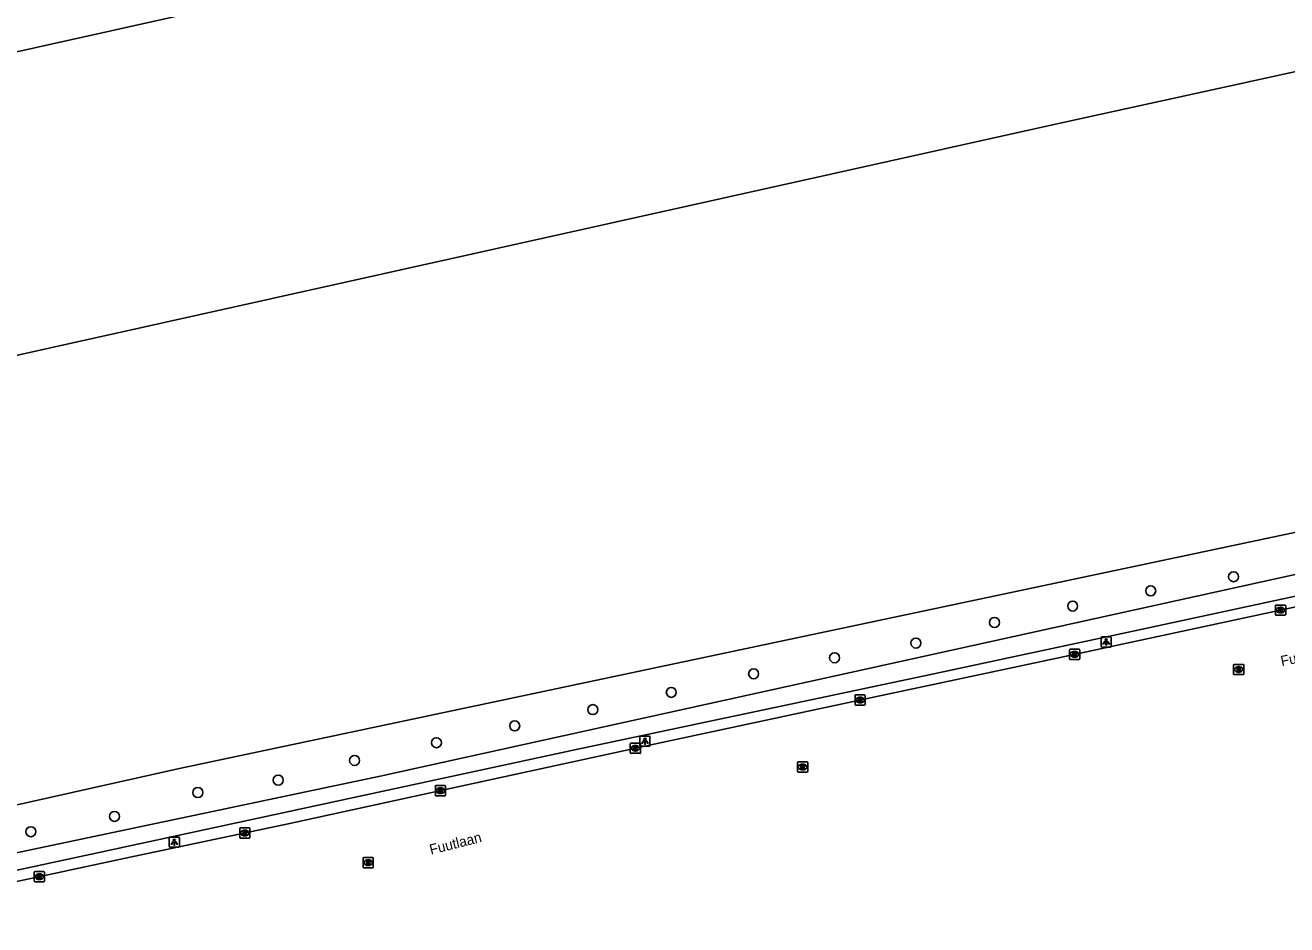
# Model space of a CAD drawing. Extents: x 161477 to 163040, y 383680 to 384868.
# Drawn here: x 161899 to 162022.7, y 383711.9 to 383800 of the extents above; entities that cross this region are included whole.
import ezdxf

# ---------------------------------------------------------------- set-up
doc = ezdxf.new("R2010")
doc.units = 0
for name, color, linetype in [('IMGEO_Boom', 7, 'Continuous'), ('IMGEO_Groenvoorziening', 7, 'Continuous'), ('IMGEO_Hek', 7, 'Continuous'), ('IMGEO_Kolk', 7, 'Continuous'), ('IMGEO_Lichtpunt', 7, 'Continuous'), ('IMGEO_Openbare_ruimte_label', 7, 'Continuous'), ('IMGEO_Pand', 7, 'Continuous'), ('IMGEO_Rijbaan_lokaal_open', 7, 'Continuous'), ('IMGEO_Rioolput', 7, 'Continuous'), ('IMGEO_Voetpad_open', 7, 'Continuous')]:
    doc.layers.add(name, color=color, linetype=linetype)

msp = doc.modelspace()

# ---------------------------------------------------------------- linework, layer by layer
at = {"layer": 'IMGEO_Boom'}
for centre in [(162017.44, 383746.01), (162009.32, 383744.63), (162001.67, 383743.13), (161994.01, 383741.53), (161986.3, 383739.51), (161978.33, 383738.07), (161970.4, 383736.5), (161962.33, 383734.68), (161954.64, 383732.99), (161946.98, 383731.4), (161939.31, 383729.75), (161931.28, 383728.01), (161923.8, 383726.08), (161915.92, 383724.87), (161907.75, 383722.53), (161899.55, 383721.03)]:
    msp.add_circle(centre, 0.489, dxfattribs=at)
at = {"layer": 'IMGEO_Groenvoorziening'}
for points in [[(162298.92, 383814.56), (162261.09, 383802.89), (162253.58, 383800.74), (162226.94, 383794.59), (162215.71, 383792.24), (162200.21, 383788.99), (162072.88, 383760.06), (162061.02, 383757.62), (162034.23, 383752.62), (161913.96, 383727.2), (161882.57, 383720.16), (161862.58, 383715.7), (161851.78, 383713.8), (161847.77, 383713.09), (161846.44, 383712.85), (161845.48, 383712.89), (161845.45, 383711.91)], [(162231.35, 383791.72), (162216.7, 383788.57), (162197.76, 383783.49), (162191.42, 383781.95), (162037.84, 383749.41), (161933.79, 383726.48), (161872.38, 383713.55)]]:
    msp.add_lwpolyline(points, dxfattribs=at)
at = {"layer": 'IMGEO_Hek'}
msp.add_lwpolyline([(161846.44, 383712.85), (161847.77, 383713.09), (161851.78, 383713.8), (161862.58, 383715.7), (161882.57, 383720.16), (161913.96, 383727.2), (162034.23, 383752.62), (162061.02, 383757.62)], dxfattribs=at)
at = {"layer": 'IMGEO_Kolk'}
for p, q in [((162021.55, 383742.31), (162021.55, 383743.17)), ((162021.62, 383743.24), (162022.47, 383743.24)), ((162022.06, 383742.46), (162022.03, 383742.46)), ((162022.04, 383743.02), (162022.06, 383743.02)), ((162022.55, 383743.17), (162022.55, 383742.31)), ((162022.47, 383742.24), (162021.62, 383742.24)), ((162001.35, 383737.98), (162001.35, 383738.83)), ((162001.43, 383738.91), (162002.28, 383738.91)), ((162001.84, 383738.69), (162001.87, 383738.69)), ((162002.36, 383738.83), (162002.36, 383737.98)), ((162002.28, 383737.91), (162001.43, 383737.91)), ((162001.86, 383738.13), (162001.84, 383738.13)), ((161980.34, 383733.5), (161980.34, 383734.36)), ((161980.41, 383734.43), (161981.27, 383734.43)), ((161980.83, 383734.21), (161980.85, 383734.21)), ((161981.34, 383734.36), (161981.34, 383733.5)), ((161981.27, 383733.43), (161980.41, 383733.43)), ((161980.85, 383733.65), (161980.82, 383733.65)), ((161958.31, 383728.78), (161958.31, 383729.63)), ((161958.39, 383729.71), (161959.24, 383729.71)), ((161958.8, 383729.49), (161958.83, 383729.49)), ((161958.82, 383728.93), (161958.8, 383728.93)), ((161959.31, 383729.63), (161959.31, 383728.78)), ((161959.24, 383728.71), (161958.39, 383728.71)), ((161939.2, 383724.62), (161939.2, 383725.48)), ((161939.27, 383725.55), (161940.12, 383725.55)), ((161939.69, 383725.33), (161939.71, 383725.33)), ((161940.2, 383725.48), (161940.2, 383724.62)), ((161940.12, 383724.55), (161939.27, 383724.55)), ((161939.71, 383724.77), (161939.68, 383724.77)), ((161920.1, 383721.4), (161920.95, 383721.4)), ((161920.03, 383720.47), (161920.03, 383721.33)), ((161920.95, 383720.4), (161920.1, 383720.4)), ((161920.51, 383721.18), (161920.54, 383721.18)), ((161920.54, 383720.62), (161920.51, 383720.62)), ((161921.03, 383721.33), (161921.03, 383720.47)), ((161899.89, 383716.19), (161899.89, 383717.05)), ((161899.96, 383717.12), (161900.82, 383717.12)), ((161900.38, 383716.9), (161900.4, 383716.9)), ((161900.89, 383717.05), (161900.89, 383716.19)), ((161900.82, 383716.12), (161899.96, 383716.12)), ((161900.4, 383716.34), (161900.38, 383716.34))]:
    msp.add_line(p, q, dxfattribs=at)
for points in [[(162021.55, 383742.31), (162021.55, 383743.17)], [(162021.62, 383743.24), (162022.47, 383743.24)], [(162021.87, 383742.94), (162021.99, 383742.94), (162021.99, 383742.79), (162022.12, 383742.94), (162022.29, 383742.94), (162022.14, 383742.79), (162022.29, 383742.54), (162022.14, 383742.54), (162022.06, 383742.7), (162021.99, 383742.64), (162021.99, 383742.54), (162021.87, 383742.54), (162021.87, 383742.94)], [(162022.55, 383743.17), (162022.55, 383742.31)], [(162022.47, 383742.24), (162021.62, 383742.24)], [(162001.35, 383737.98), (162001.35, 383738.83)], [(162001.43, 383738.91), (162002.28, 383738.91)], [(162002.36, 383738.83), (162002.36, 383737.98)], [(162002.28, 383737.91), (162001.43, 383737.91)], [(162001.67, 383738.61), (162001.8, 383738.61), (162001.8, 383738.46), (162001.93, 383738.61), (162002.09, 383738.61), (162001.95, 383738.46), (162002.1, 383738.21), (162001.95, 383738.21), (162001.86, 383738.37), (162001.8, 383738.31), (162001.8, 383738.21), (162001.67, 383738.21), (162001.67, 383738.61)], [(161980.34, 383733.5), (161980.34, 383734.36)], [(161980.41, 383734.43), (161981.27, 383734.43)], [(161980.66, 383734.13), (161980.78, 383734.13), (161980.78, 383733.98), (161980.91, 383734.13), (161981.08, 383734.13), (161980.93, 383733.98), (161981.08, 383733.73), (161980.93, 383733.73), (161980.85, 383733.89), (161980.78, 383733.83), (161980.78, 383733.73), (161980.66, 383733.73), (161980.66, 383734.13)], [(161981.34, 383734.36), (161981.34, 383733.5)], [(161981.27, 383733.43), (161980.41, 383733.43)], [(161958.31, 383728.78), (161958.31, 383729.63)], [(161958.39, 383729.71), (161959.24, 383729.71)], [(161958.63, 383729.41), (161958.76, 383729.41), (161958.76, 383729.25), (161958.89, 383729.41), (161959.05, 383729.41), (161958.9, 383729.26), (161959.06, 383729.01), (161958.9, 383729.01), (161958.82, 383729.17), (161958.76, 383729.1), (161958.76, 383729.01), (161958.63, 383729.01), (161958.63, 383729.41)], [(161959.31, 383729.63), (161959.31, 383728.78)], [(161959.24, 383728.71), (161958.39, 383728.71)], [(161939.2, 383724.62), (161939.2, 383725.48)], [(161939.27, 383725.55), (161940.12, 383725.55)], [(161939.52, 383725.25), (161939.64, 383725.25), (161939.64, 383725.1), (161939.77, 383725.25), (161939.94, 383725.25), (161939.79, 383725.1), (161939.94, 383724.85), (161939.79, 383724.85), (161939.71, 383725.01), (161939.64, 383724.95), (161939.64, 383724.85), (161939.52, 383724.85), (161939.52, 383725.25)], [(161940.2, 383725.48), (161940.2, 383724.62)], [(161940.12, 383724.55), (161939.27, 383724.55)], [(161920.1, 383721.4), (161920.95, 383721.4)], [(161920.03, 383720.47), (161920.03, 383721.33)], [(161920.95, 383720.4), (161920.1, 383720.4)], [(161920.35, 383721.1), (161920.47, 383721.1), (161920.47, 383720.95), (161920.6, 383721.1), (161920.76, 383721.1), (161920.62, 383720.95), (161920.77, 383720.7), (161920.62, 383720.7), (161920.53, 383720.86), (161920.47, 383720.8), (161920.47, 383720.7), (161920.35, 383720.7), (161920.35, 383721.1)], [(161921.03, 383721.33), (161921.03, 383720.47)], [(161899.89, 383716.19), (161899.89, 383717.05)], [(161899.96, 383717.12), (161900.82, 383717.12)], [(161900.21, 383716.82), (161900.33, 383716.82), (161900.33, 383716.67), (161900.46, 383716.82), (161900.63, 383716.82), (161900.48, 383716.67), (161900.63, 383716.42), (161900.48, 383716.42), (161900.4, 383716.59), (161900.33, 383716.52), (161900.33, 383716.42), (161900.21, 383716.42), (161900.21, 383716.82)], [(161900.89, 383717.05), (161900.89, 383716.19)], [(161900.82, 383716.12), (161899.96, 383716.12)]]:
    msp.add_lwpolyline(points, dxfattribs=at)
for centre, start, end in [((162021.62, 383743.16), 91.552, 178.448), ((162021.62, 383743.16), 91.552, 178.448), ((162022.47, 383743.16), 1.552, 88.448), ((162022.47, 383743.16), 1.552, 88.448), ((162021.62, 383742.32), 181.552, 268.448), ((162021.62, 383742.32), 181.552, 268.448), ((162022.47, 383742.32), 271.552, 358.448), ((162022.47, 383742.32), 271.552, 358.448), ((162001.43, 383738.83), 91.552, 178.448), ((162001.43, 383738.83), 91.552, 178.448), ((162002.28, 383738.83), 1.552, 88.448), ((162002.28, 383738.83), 1.552, 88.448), ((162001.43, 383737.98), 181.552, 268.448), ((162001.43, 383737.98), 181.552, 268.448), ((162002.28, 383737.98), 271.552, 358.448), ((162002.28, 383737.98), 271.552, 358.448), ((161980.41, 383734.35), 91.552, 178.448), ((161980.41, 383734.35), 91.552, 178.448), ((161981.26, 383734.35), 1.552, 88.448), ((161981.26, 383734.35), 1.552, 88.448), ((161980.41, 383733.5), 181.552, 268.448), ((161980.41, 383733.5), 181.552, 268.448), ((161981.26, 383733.5), 271.552, 358.448), ((161981.26, 383733.5), 271.552, 358.448), ((161958.39, 383729.63), 91.552, 178.448), ((161958.39, 383729.63), 91.552, 178.448), ((161959.24, 383729.63), 1.552, 88.448), ((161959.24, 383729.63), 1.552, 88.448), ((161958.39, 383728.78), 181.552, 268.448), ((161958.39, 383728.78), 181.552, 268.448), ((161959.24, 383728.78), 271.552, 358.448), ((161959.24, 383728.78), 271.552, 358.448), ((161939.27, 383725.47), 91.552, 178.448), ((161939.27, 383725.47), 91.552, 178.448), ((161940.12, 383725.47), 1.552, 88.448), ((161940.12, 383725.47), 1.552, 88.448), ((161939.27, 383724.63), 181.552, 268.448), ((161939.27, 383724.63), 181.552, 268.448), ((161940.12, 383724.63), 271.552, 358.448), ((161940.12, 383724.63), 271.552, 358.448), ((161920.1, 383721.32), 91.552, 178.448), ((161920.1, 383721.32), 91.552, 178.448), ((161920.95, 383721.32), 1.552, 88.448), ((161920.95, 383721.32), 1.552, 88.448), ((161920.1, 383720.48), 181.552, 268.448), ((161920.1, 383720.48), 181.552, 268.448), ((161920.95, 383720.48), 271.552, 358.448), ((161920.95, 383720.48), 271.552, 358.448), ((161899.97, 383717.05), 91.552, 178.448), ((161899.97, 383717.05), 91.552, 178.448), ((161900.81, 383717.05), 1.552, 88.448), ((161900.81, 383717.05), 1.552, 88.448), ((161899.97, 383716.2), 181.552, 268.448), ((161899.97, 383716.2), 181.552, 268.448), ((161900.81, 383716.2), 271.552, 358.448), ((161900.81, 383716.2), 271.552, 358.448)]:
    msp.add_arc(centre, 0.0765, start, end, dxfattribs=at)
for centre, major_axis, ratio, start_param, end_param in [((162022.03, 383742.74), (-0.387, 0.002), 0.722429, 4.712389, 7.853982), ((162022.06, 383742.74), (-0.39, 0.002), 0.717154, 1.570796, 4.712389), ((162001.84, 383738.41), (-0.387, 0.002), 0.722429, 4.712389, 7.853982), ((162001.87, 383738.41), (-0.39, 0.002), 0.717154, 1.570796, 4.712389), ((161980.83, 383733.93), (-0.387, 0.002), 0.722429, 4.712389, 7.853982), ((161980.85, 383733.93), (-0.39, 0.002), 0.717154, 1.570796, 4.712389), ((161958.8, 383729.21), (-0.387, 0.002), 0.722429, 4.712389, 7.853982), ((161958.82, 383729.21), (-0.39, 0.002), 0.717154, 1.570796, 4.712389), ((161939.68, 383725.05), (-0.387, 0.002), 0.722429, 4.712389, 7.853982), ((161939.71, 383725.05), (-0.39, 0.002), 0.717154, 1.570796, 4.712389), ((161920.51, 383720.9), (-0.387, 0.002), 0.722429, 4.712389, 7.853982), ((161920.54, 383720.9), (-0.39, 0.002), 0.717154, 1.570796, 4.712389), ((161900.38, 383716.62), (-0.387, 0.002), 0.722429, 4.712389, 7.853982), ((161900.4, 383716.62), (-0.39, 0.002), 0.717154, 1.570796, 4.712389)]:
    msp.add_ellipse(centre, major_axis=major_axis, ratio=ratio, start_param=start_param, end_param=end_param, dxfattribs=at)
at = {"layer": 'IMGEO_Lichtpunt'}
for p, q in [((162004.45, 383740.02), (162004.45, 383739.21)), ((162004.45, 383740.02), (162004.45, 383739.21)), ((162005.36, 383740.11), (162004.55, 383740.11)), ((162005.36, 383740.11), (162004.55, 383740.11)), ((162005.45, 383739.21), (162005.45, 383740.02)), ((162005.45, 383739.21), (162005.45, 383740.02)), ((162004.55, 383739.11), (162005.36, 383739.11)), ((162004.55, 383739.11), (162005.36, 383739.11)), ((161959.25, 383730.3), (161959.25, 383729.5)), ((161959.25, 383730.3), (161959.25, 383729.5)), ((161960.15, 383730.4), (161959.34, 383730.4)), ((161960.15, 383730.4), (161959.34, 383730.4)), ((161960.24, 383729.5), (161960.24, 383730.3)), ((161960.24, 383729.5), (161960.24, 383730.3)), ((161959.34, 383729.4), (161960.15, 383729.4)), ((161959.34, 383729.4), (161960.15, 383729.4)), ((161913.11, 383720.42), (161913.11, 383719.61)), ((161913.11, 383720.42), (161913.11, 383719.61)), ((161914.01, 383720.51), (161913.21, 383720.51)), ((161914.01, 383720.51), (161913.21, 383720.51)), ((161914.11, 383719.61), (161914.11, 383720.42)), ((161914.11, 383719.61), (161914.11, 383720.42)), ((161913.21, 383719.51), (161914.01, 383719.51)), ((161913.21, 383719.51), (161914.01, 383719.51))]:
    msp.add_line(p, q, dxfattribs=at)
for points in [[(162004.83, 383739.68), (162004.87, 383739.65), (162004.68, 383739.39), (162004.64, 383739.42), (162004.83, 383739.68)], [(162004.93, 383739.63), (162004.98, 383739.63), (162004.98, 383739.31), (162004.93, 383739.31), (162004.93, 383739.63)], [(162005.04, 383739.65), (162005.08, 383739.68), (162005.27, 383739.42), (162005.23, 383739.39), (162005.04, 383739.65)], [(161959.62, 383729.97), (161959.66, 383729.94), (161959.47, 383729.68), (161959.43, 383729.7), (161959.62, 383729.97)], [(161959.72, 383729.92), (161959.77, 383729.92), (161959.77, 383729.6), (161959.72, 383729.6), (161959.72, 383729.92)], [(161959.83, 383729.94), (161959.87, 383729.97), (161960.06, 383729.7), (161960.02, 383729.68), (161959.83, 383729.94)], [(161913.49, 383720.08), (161913.53, 383720.05), (161913.34, 383719.79), (161913.3, 383719.82), (161913.49, 383720.08)], [(161913.59, 383720.03), (161913.64, 383720.03), (161913.64, 383719.71), (161913.59, 383719.71), (161913.59, 383720.03)], [(161913.7, 383720.05), (161913.74, 383720.08), (161913.92, 383719.82), (161913.89, 383719.79), (161913.7, 383720.05)]]:
    msp.add_lwpolyline(points, dxfattribs=at)
for centre in [(162004.95, 383739.81), (161959.75, 383730.1), (161913.61, 383720.21)]:
    msp.add_circle(centre, 0.0994, dxfattribs=at)
for centre, start, end in [((162004.55, 383740.02), 90, 180), ((162004.55, 383740.02), 90, 180), ((162005.36, 383740.02), 0, 90), ((162005.36, 383740.02), 0, 90), ((162004.55, 383739.21), 180, 270), ((162004.55, 383739.21), 180, 270), ((162005.36, 383739.21), 270, 0), ((162005.36, 383739.21), 270, 360), ((161959.34, 383730.3), 90, 180), ((161959.34, 383730.3), 90, 180), ((161960.15, 383730.3), 0, 90), ((161960.15, 383730.3), 0, 90), ((161959.34, 383729.5), 180, 270), ((161959.34, 383729.5), 180, 270), ((161960.15, 383729.5), 270, 0), ((161960.15, 383729.5), 270, 360), ((161913.21, 383720.42), 90, 180), ((161913.21, 383720.42), 90, 180), ((161914.01, 383720.42), 0, 90), ((161914.01, 383720.42), 0, 90), ((161913.21, 383719.61), 180, 270), ((161913.21, 383719.61), 180, 270), ((161914.01, 383719.61), 270, 0), ((161914.01, 383719.61), 270, 360)]:
    msp.add_arc(centre, 0.0946, start, end, dxfattribs=at)
at = {"layer": 'IMGEO_Pand'}
for points in [[(161884.31, 383793.82), (161888.73, 383773.98), (161886.05, 383773.38), (161886.3, 383772.28), (161885.88, 383772.17), (161885.51, 383773.82), (161859.41, 383768), (161862.46, 383754.35), (161888.64, 383760.19), (161888.12, 383762.5), (161887.37, 383765.86), (161890.33, 383766.52), (161890.45, 383765.98), (162000, 383790.34), (162126.91, 383818.18), (162134.33, 383819.8), (162130.48, 383837.21), (162140.9, 383839.53), (162139.81, 383844.85)], [(162088.04, 383839.79), (162000, 383820.13), (161884.78, 383794.45), (161884.66, 383795.01), (161884.29, 383794.93), (161884.34, 383794.72)]]:
    msp.add_lwpolyline(points, dxfattribs=at)
at = {"layer": 'IMGEO_Rijbaan_lokaal_open'}
msp.add_lwpolyline([(162038.61, 383746.29), (162000, 383738.01), (161982.31, 383734.24), (161961.39, 383729.76), (161941.41, 383725.42), (161924.76, 383721.79), (161909.3, 383718.55), (161896.63, 383715.81)], dxfattribs=at)
at = {"layer": 'IMGEO_Rioolput'}
for p, q in [((162017.45, 383736.49), (162017.45, 383737.35)), ((162017.52, 383737.42), (162018.37, 383737.42)), ((162018.37, 383736.42), (162017.52, 383736.42)), ((162017.93, 383737.2), (162017.96, 383737.2)), ((162017.96, 383736.64), (162017.93, 383736.64)), ((162018.45, 383737.35), (162018.45, 383736.49)), ((161974.7, 383726.95), (161974.7, 383727.8)), ((161974.77, 383727.88), (161975.62, 383727.88)), ((161975.18, 383727.65), (161975.21, 383727.65)), ((161975.7, 383727.8), (161975.7, 383726.95)), ((161975.62, 383726.87), (161974.77, 383726.87)), ((161975.21, 383727.1), (161975.18, 383727.1)), ((161932.12, 383717.58), (161932.12, 383718.43)), ((161932.19, 383718.5), (161933.04, 383718.5)), ((161932.6, 383718.28), (161932.63, 383718.28)), ((161932.63, 383717.72), (161932.6, 383717.72)), ((161933.12, 383718.43), (161933.12, 383717.58)), ((161933.04, 383717.5), (161932.19, 383717.5))]:
    msp.add_line(p, q, dxfattribs=at)
for points in [[(162017.45, 383736.49), (162017.45, 383737.35)], [(162017.52, 383737.42), (162018.37, 383737.42)], [(162018.37, 383736.42), (162017.52, 383736.42)], [(162018.03, 383737.12), (162017.78, 383737.12), (162017.78, 383736.72)], [(162017.78, 383736.72), (162017.91, 383736.72), (162017.91, 383736.88), (162017.92, 383736.88)], [(162017.96, 383737.04), (162017.91, 383737.04), (162017.91, 383736.96)], [(162017.91, 383736.96), (162017.96, 383736.96)], [(162017.96, 383736.85), (162018.04, 383736.72), (162018.17, 383736.72), (162018.11, 383736.85)], [(162018.45, 383737.35), (162018.45, 383736.49)], [(161974.7, 383726.95), (161974.7, 383727.8)], [(161974.77, 383727.88), (161975.62, 383727.88)], [(161975.29, 383727.57), (161975.03, 383727.57), (161975.03, 383727.17)], [(161975.7, 383727.8), (161975.7, 383726.95)], [(161975.62, 383726.87), (161974.77, 383726.87)], [(161975.03, 383727.17), (161975.16, 383727.17), (161975.16, 383727.34), (161975.17, 383727.34)], [(161975.21, 383727.49), (161975.16, 383727.49), (161975.16, 383727.41)], [(161975.16, 383727.41), (161975.21, 383727.41)], [(161975.21, 383727.31), (161975.29, 383727.17), (161975.43, 383727.17), (161975.36, 383727.3)], [(161932.12, 383717.58), (161932.12, 383718.43)], [(161932.19, 383718.5), (161933.04, 383718.5)], [(161932.71, 383718.2), (161932.45, 383718.2), (161932.45, 383717.8)], [(161932.45, 383717.8), (161932.58, 383717.8), (161932.58, 383717.96), (161932.59, 383717.96)], [(161932.63, 383718.12), (161932.58, 383718.12), (161932.58, 383718.04)], [(161932.58, 383718.04), (161932.63, 383718.04)], [(161932.63, 383717.93), (161932.71, 383717.8), (161932.85, 383717.8), (161932.78, 383717.93)], [(161933.12, 383718.43), (161933.12, 383717.58)], [(161933.04, 383717.5), (161932.19, 383717.5)]]:
    msp.add_lwpolyline(points, dxfattribs=at)
for centre, radius, start, end in [((162017.52, 383737.35), 0.0765, 91.552, 178.448), ((162017.52, 383737.35), 0.0765, 91.552, 178.448), ((162017.52, 383736.5), 0.0765, 181.552, 268.448), ((162017.52, 383736.5), 0.0765, 181.552, 268.448), ((162017.92, 383736.83), 0.0533, 26.0293, 88.6989), ((162017.97, 383736.94), 0.0964, 77.0061, 93.1865), ((162017.94, 383737.15), 0.19, 274.7715, 282.9687), ((162017.98, 383737), 0.0378, 276.6634, 79.6772), ((162018.03, 383737.01), 0.109, 350.3612, 89.416), ((162018.03, 383737.01), 0.112, 277.5842, 350.9817), ((162018.02, 383736.79), 0.108, 29.5134, 73.7905), ((162018.37, 383737.35), 0.0765, 1.552, 88.448), ((162018.37, 383737.35), 0.0765, 1.552, 88.448), ((162018.37, 383736.5), 0.0765, 271.552, 358.448), ((162018.37, 383736.5), 0.0765, 271.552, 358.448), ((161974.77, 383727.8), 0.0765, 91.552, 178.448), ((161974.77, 383727.8), 0.0765, 91.552, 178.448), ((161975.28, 383727.46), 0.109, 350.3612, 89.416), ((161975.62, 383727.8), 0.0765, 1.552, 88.448), ((161975.62, 383727.8), 0.0765, 1.552, 88.448), ((161974.77, 383726.95), 0.0765, 181.552, 268.448), ((161974.77, 383726.95), 0.0765, 181.552, 268.448), ((161975.17, 383727.28), 0.0533, 26.0293, 88.6989), ((161975.22, 383727.4), 0.0964, 77.0061, 93.1865), ((161975.19, 383727.6), 0.19, 274.7715, 282.9687), ((161975.23, 383727.45), 0.0378, 276.6634, 79.6772), ((161975.28, 383727.46), 0.112, 277.5842, 350.9817), ((161975.27, 383727.25), 0.108, 29.5134, 73.7905), ((161975.62, 383726.95), 0.0765, 271.552, 358.448), ((161975.62, 383726.95), 0.0765, 271.552, 358.448), ((161932.19, 383718.43), 0.0765, 91.552, 178.448), ((161932.19, 383718.43), 0.0765, 91.552, 178.448), ((161932.59, 383717.91), 0.0533, 26.0293, 88.6989), ((161932.64, 383718.02), 0.0964, 77.0061, 93.1865), ((161932.61, 383718.23), 0.19, 274.7715, 282.9687), ((161932.65, 383718.08), 0.0378, 276.6634, 79.6772), ((161932.7, 383718.09), 0.109, 350.3612, 89.416), ((161932.7, 383718.09), 0.112, 277.5842, 350.9817), ((161932.69, 383717.87), 0.108, 29.5134, 73.7905), ((161933.04, 383718.43), 0.0765, 1.552, 88.448), ((161933.04, 383718.43), 0.0765, 1.552, 88.448), ((161932.19, 383717.58), 0.0765, 181.552, 268.448), ((161932.19, 383717.58), 0.0765, 181.552, 268.448), ((161933.04, 383717.58), 0.0765, 271.552, 358.448), ((161933.04, 383717.58), 0.0765, 271.552, 358.448)]:
    msp.add_arc(centre, radius, start, end, dxfattribs=at)
for centre, major_axis, ratio, start_param, end_param in [((162017.93, 383736.92), (-0.387, 0.002), 0.722429, 4.712389, 7.853982), ((162017.96, 383736.92), (-0.39, 0.002), 0.717154, 1.570796, 4.712389), ((161975.18, 383727.37), (-0.387, 0.002), 0.722429, 4.712389, 7.853982), ((161975.21, 383727.37), (-0.39, 0.002), 0.717154, 1.570796, 4.712389), ((161932.6, 383718), (-0.387, 0.002), 0.722429, 4.712389, 7.853982), ((161932.63, 383718), (-0.39, 0.002), 0.717154, 1.570796, 4.712389)]:
    msp.add_ellipse(centre, major_axis=major_axis, ratio=ratio, start_param=start_param, end_param=end_param, dxfattribs=at)
at = {"layer": 'IMGEO_Voetpad_open'}
msp.add_lwpolyline([(161872.38, 383713.55), (161876.5, 383713.96), (161886.43, 383715.07), (161895.43, 383716.66), (161904.89, 383718.7), (161934.1, 383725.01), (161953.18, 383729.12), (161987.59, 383736.39), (162007.91, 383740.73), (162033.22, 383746.19), (162060.49, 383752.12), (162097.3, 383759.98), (162118.07, 383764.45), (162141.54, 383769.48), (162180.49, 383777.87), (162190.22, 383779.97), (162198.07, 383781.8), (162206.11, 383783.95), (162214.63, 383786.44), (162216.75, 383787.01), (162217.08, 383787.12), (162231.35, 383791.72)], dxfattribs=at)

# ---------------------------------------------------------------- texts
at = {"layer": 'IMGEO_Openbare_ruimte_label'}
for rotation, p in [(11.9506, (162022.17, 383737.24)), (14.1751, (161938.77, 383718.77))]:
    msp.add_text('Fuutlaan', height=1, rotation=rotation, dxfattribs=at).set_placement(p)

doc.saveas('drawing.dxf')
